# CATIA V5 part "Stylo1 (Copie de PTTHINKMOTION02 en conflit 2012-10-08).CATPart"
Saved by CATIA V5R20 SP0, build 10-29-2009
Part number: Stylo1
Bounding box of the stored display mesh (mm): x -5 to 5, y -21.75 to 25, z -5 to 5
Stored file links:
  D:\Dropbox\IAO\IAO_2010\iao\IAO OK\IAO_2010_1447_melguidj\Catia_1447_melguidj\Stylo1.CATPart
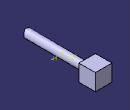
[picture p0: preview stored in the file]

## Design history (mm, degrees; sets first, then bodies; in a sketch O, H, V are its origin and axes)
Body1 (main body)
  Sketch1 on xy-plane, origin (0, 0, 0), H (1, 0, 0), V (0, 1, 0)
    point P1 (0, 15)
    line L1 (0, 15) -> (-2.5, 15)
    line L2 (-2.5, 15) -> (-2.5, -30)
    line L3 (0, -30) -> (0, 15)
    point P5 (0, 15)
    line L4 (0, -30) -> (-2.5, -30)
    distance L2 L3 = 2.5
    distance L1 H = 15
    distance L4 H = 30
    coincidence: P1 V, P5 P1
    horizontal: L1 H, L4 H
    vertical: L2 V, L3 V
  Shaft1: profile Sketch1, axis Sketch1.L3, angle 360
  Sketch2 on xy-plane, origin (0, 0, 0), H (1, 0, 0), V (0, 1, 0)
    point P1 (0, 0)
    point P2 (0, 10)
    distance P2 H = 10
    coincidence: P1 O, P2 V
  Sketch3 on face of Shaft1 from Sketch1.L1, origin (0, 15, 0), H (-1, 0, 0), V (0, 0, 1)
    line L1 (-5, 5) -> (5, 5)
    line L2 (5, 5) -> (5, -5)
    line L3 (5, -5) -> (-5, -5)
    line L4 (-5, -5) -> (-5, 5)
    length L2 = 10
    distance L1 H = 5
    length L1 = 10
    distance L2 V = 5
    horizontal: L1 H, L3 H
    vertical: L2 V, L4 V
  Pad1: profile Sketch3, direction (0, 1, 0), length 10
  Sketch4 on xy-plane, origin (0, 0, 0), H (1, 0, 0), V (0, 1, 0)
    arc A1 centre (0, -17.75) radius 4 from (-4, -17.75) to (0, -21.75) ccw
    point P1 (0, -17.75)
    point P2 (0, -21.75)
    point P3 (-4, -17.75)
    point P4 (-4, -17.75)
    line L1 (-4, -17.75) -> (-4, -13.6979)
    point P5 (-4, -13.6979)
    line L2 (-4, -13.6979) -> (-8.3161, -13.6979)
    point P6 (-8.3161, -13.6979)
    line L3 (-8.3161, -13.6979) -> (-8.3161, -43.1519)
    point P7 (-8.3161, -43.1519)
    line L4 (-8.3161, -43.1519) -> (0, -43.1519)
    axis line L5 (0, -5.8734) -> (0, -36.7849)
    point P8 (0, -5.8734)
    point P10 (0, -43.1519)
    point P12 (0, -21.75)
    point P13 (4, -17.75)
    point P14 (4, -17.75)
    point P15 (4, -13.6979)
    point P16 (8.3161, -13.6979)
    point P17 (8.3161, -43.1519)
    point P18 (0, -43.1519)
    arc A2 centre (0, -17.75) radius 4 from (4, -17.75) to (0, -21.75) cw
    line L6 (4, -17.75) -> (4, -13.6979)
    line L7 (4, -13.6979) -> (8.3161, -13.6979)
    line L8 (8.3161, -13.6979) -> (8.3161, -43.1519)
    line L9 (8.3161, -43.1519) -> (0, -43.1519)
    distance L1 L5 = 4
    coincidence: P1 V, P2 V, P4 A1, P8 V, L5 P10, P3 P4, P2 P12, P10 P18, P13 P14
    vertical: L1 V, L3 V, L5 V
    horizontal: L2 H, L4 H
    tangency: L1 A1
    symmetry: P2 P12 L5, P3 P13 L5, P4 P14 L5, P5 P15 L5, P6 P16 L5, P7 P17 L5, P10 P18 L5, A1 A2 L5, L1 L6 L5, L2 L7 L5, L3 L8 L5, L4 L9 L5
  Pocket1: profile Sketch4, direction (0, 0, -1), length 10, mirrored extent
  Sketch5 on xy-plane, origin (0, 0, 0), H (1, 0, 0), V (0, 1, 0)
    arc A1 centre (-0.0001, -17.7509) radius 4 from (-4.0001, -17.7509) to (3.9999, -17.7509) ccw
    reference projected arc E1 centre (-0.0001, -17.7504) radius 3.9996 from (-3.9997, -17.7504) to (-0.0001, -21.75) ccw from edge [face of Pocket1 from Sketch4.A1 | face of Shaft1 from Sketch1.L2]
    radius A1 = 4
    distance A1 E1 = 0
  DatumCurve1
  Sketch6 on xy-plane, origin (0, 0, 0), H (1, 0, 0), V (0, 1, 0)
    point P1 (-1.0619, -21.6065)
    reference projected arc E1 centre (-5.0438, -36.0683) radius 15 from (1.1053, -22.3866) to (4.6501, -47.515) ccw from edge of DatumCurve1
    reference projected arc E2 centre (-0.0001, -17.7504) radius 3.9996 from (-3.9997, -17.7504) to (-0.0001, -21.75) ccw from edge [face of Pocket1 from Sketch4.A1 | face of Shaft1 from Sketch1.L2]
    coincidence: P1 E1, P1 E2
  DatumCurve2 to DatumCurve7
  DatumPoint1
  DatumCurve8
